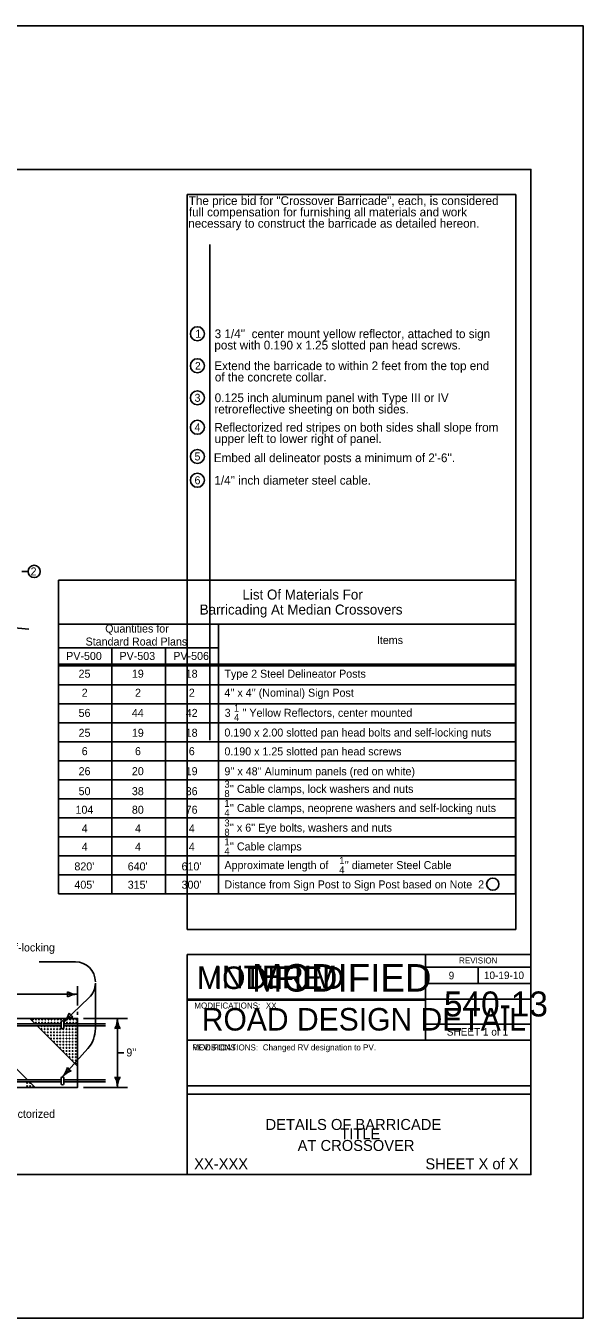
# Model space of a CAD drawing. Extents: x 228 to 3572, y -1307 to 1277.
# Drawn here: x 2457 to 3572, y -1307 to 1277 of the extents above; entities that cross this region are included whole.
import ezdxf

# ---------------------------------------------------------------- set-up
doc = ezdxf.new("R2010")
doc.units = 0
for name, color, linetype in [('dsnNonPlotable', 7, 'Continuous'), ('dsnShtPlotShapeBatchPrint', 7, 'Continuous'), ('dsnStdBlock', 7, 'Continuous'), ('dsnstdblockInterim', 7, 'Continuous'), ('dsnStdBlockModified', 7, 'Continuous'), ('dsnStdBlockNotModified', 7, 'Continuous'), ('dsnStdBorder', 7, 'Continuous'), ('dsnStdDimension', 7, 'Continuous'), ('Level 1', 7, 'Continuous'), ('Level 15', 7, 'Continuous'), ('Level 2', 7, 'Continuous'), ('Level 3', 7, 'Continuous')]:
    doc.layers.add(name, color=color, linetype=linetype)

msp = doc.modelspace()

# ---------------------------------------------------------------- linework, layer by layer
at = {"layer": 'dsnNonPlotable'}
for p, q in [((2779.5, 940), (2779.5, -530)), ((3437.5, 940), (2779.5, 940)), ((3437.5, 940), (3437.5, -530)), ((2824.5, 840), (2824.5, -151.5)), ((3437.5, -530), (2779.5, -530))]:
    msp.add_line(p, q, dxfattribs=at)
at = {"layer": 'dsnShtPlotShapeBatchPrint'}
msp.add_lwpolyline([(228, -1307), (3572, -1307), (3572, 1277), (228, 1277)], close=True, dxfattribs=at)
at = {"layer": 'dsnStdBlock'}
for p, q in [((3256.6, -580), (3256.6, -671.3)), ((3256.6, -604.9), (3467.5, -604.9)), ((3362, -604.9), (3362, -638.1)), ((3256.6, -638.1), (3467.5, -638.1)), ((2779.5, -671.3), (3256.6, -671.3)), ((3256.6, -671.3), (3256.6, -751.3)), ((3467.5, -719.1), (3256.6, -719.1)), ((2779.5, -751.3), (3467.5, -751.3)), ((2779.5, -842.3), (3467.5, -842.3))]:
    msp.add_line(p, q, dxfattribs=at)
msp.add_lwpolyline([(2779.5, -580), (3467.5, -580), (3467.5, -1020), (2779.5, -1020)], close=True, dxfattribs=at)
at = {"layer": 'dsnStdBorder'}
msp.add_lwpolyline([(332.5, 990), (3467.5, 990), (3467.5, -1020), (332.5, -1020)], close=True, dxfattribs=at)
at = {"layer": 'dsnStdDimension'}
for p, q in [((2461.1, 186.1), (2448.9, 186.1)), ((2483.6, -594.4), (2555.8, -594.4)), ((2560, -681.8), (2560, -643.5)), ((2595.8, -636.9), (2595.8, -727.9)), ((2560, -659.5), (1828, -659.5)), ((2532.4, -714.7), (2583.5, -665.8)), ((2560, -700.2), (2560, -694.3)), ((2572, -707.5), (2660, -707.5)), ((2640, -707.5), (2640, -845.5)), ((2530, -824.5), (2580.6, -767.9)), ((2652.4, -776.5), (2640, -776.5)), ((2572, -845.5), (2660, -845.5))]:
    msp.add_line(p, q, dxfattribs=at)
for centre, radius, start, end in [((2555.8, -634.4), 40, 0, 90), ((2555.8, -636.9), 40, 313.7111, 0), ((2523.8, -659.5), 16.7, 342.2666, 17.7333), ((2560, -616.3), 43.2, 241.9275, 270), ((2560, -702.6), 43.2, 90, 118.0725), ((2502.5, -683.4), 43.2, 313.7158, 341.7883), ((2558.6, -689.6), 16.7, 205.9824, 241.4491), ((2562.2, -745.9), 43.2, 105.6433, 133.7158), ((2596.8, -707.5), 43.2, 331.9275, 0), ((2683.2, -707.5), 43.2, 180, 208.0725), ((2535.8, -727.9), 60, 318.1928, 0), ((2640, -743.7), 16.7, 72.2666, 107.7334), ((2497.8, -795.7), 43.2, 318.1946, 346.2671), ((2562.2, -853.2), 43.2, 110.1221, 138.1946), ((2554.1, -797.5), 16.7, 210.4612, 245.9279), ((2640, -809.3), 16.7, 252.2666, 287.7333), ((2596.8, -845.5), 43.2, 0, 28.0725), ((2683.2, -845.5), 43.2, 151.9275, 180)]:
    msp.add_arc(centre, radius, start, end, dxfattribs=at)
at = {"layer": 'Level 15'}
for p, q in [((2779.5, -669.1), (3467.5, -669.1)), ((2779.5, -859.1), (3467.5, -859.1))]:
    msp.add_line(p, q, dxfattribs=at)
msp.add_lwpolyline([(2779.5, -580), (3467.5, -580), (3467.5, -1020), (2779.5, -1020)], close=True, dxfattribs=at)
at = {"layer": 'Level 2'}
for p, q in [((2522, 168.9), (2522, -458.4)), ((2522, 168.9), (3436.6, 168.9)), ((3436.6, 168.9), (3436.6, -458.4)), ((2018.9, 110), (2462.6, 70.9)), ((2522, 80.9), (3436.6, 80.9)), ((2842, 80.9), (2842, -458.4)), ((2522, 33.6), (2842, 33.6)), ((2629, 33.6), (2629, -458.4)), ((2736, 33.6), (2736, -458.4)), ((2522, 0.6), (3436.6, 0.6)), ((2522, -2.4), (3436.6, -2.4)), ((2522, -40.4), (3436.6, -40.4)), ((2522, -78.4), (3436.6, -78.4)), ((2522, -116.4), (3436.6, -116.4)), ((2522, -154.4), (3436.6, -154.4)), ((2522, -192.4), (3436.6, -192.4)), ((2522, -230.4), (3436.6, -230.4)), ((2522, -268.4), (3436.6, -268.4)), ((2522, -306.4), (3436.6, -306.4)), ((2522, -344.4), (3436.6, -344.4)), ((2522, -382.4), (3436.6, -382.4)), ((2522, -420.4), (3436.6, -420.4)), ((2522, -458.4), (3436.6, -458.4)), ((2475.3, -718.4), (2348, -718.4)), ((2460.2, -830.6), (2352, -722.4)), ((2479.3, -722.4), (2352, -722.4)), ((2464.4, -707.5), (2475.3, -718.4)), ((2560, -707.5), (2464.4, -707.5)), ((2475.1, -707.5), (2560, -707.5)), ((2475.3, -718.4), (2527.6, -718.4)), ((2527.6, -722.4), (2479.3, -722.4)), ((2479.3, -722.4), (2560, -803.1)), ((2527.6, -718.4), (2527.6, -714.7)), ((2527.6, -722.4), (2527.6, -718.4)), ((2527.6, -726.1), (2527.6, -722.4)), ((2532.4, -714.7), (2532.4, -718.4)), ((2616.1, -718.4), (2532.4, -718.4)), ((2532.4, -722.4), (2532.4, -718.4)), ((2532.4, -718.4), (2560, -718.4)), ((2616.1, -722.4), (2532.4, -722.4)), ((2560, -722.4), (2532.4, -722.4)), ((2532.4, -722.4), (2532.4, -726.1)), ((2560, -707.5), (2560, -718.4)), ((2560, -718.4), (2560, -707.5)), ((2560, -722.4), (2560, -749.9)), ((2560, -803.1), (2560, -722.4)), ((2527.6, -838.3), (2527.6, -826.9)), ((2532.4, -838.3), (2532.4, -826.9)), ((2332.9, -830.6), (2460.2, -830.6)), ((2464.2, -834.6), (2336.9, -834.6)), ((2464.4, -845.5), (2337.1, -845.5)), ((2347.8, -845.5), (2475.1, -845.5)), ((2527.6, -834.6), (2348, -834.6)), ((2527.6, -830.6), (2352, -830.6)), ((2475.1, -845.5), (2464.2, -834.6)), ((2616.1, -830.6), (2532.4, -830.6)), ((2616.1, -834.6), (2532.4, -834.6)), ((2560, -837.9), (2560, -845.5))]:
    msp.add_line(p, q, dxfattribs=at)
msp.add_lwpolyline([(1828, -707.5), (2560, -707.5), (2560, -845.5), (1828, -845.5)], close=True, dxfattribs=at)
for centre, radius in [((2799.9, 661.3), 14), ((2799.9, 597.3), 14), ((2799.9, 533.3), 14), ((2799.9, 474.3), 14), ((2799.9, 416), 14), ((2799.9, 368.4), 14), ((2473.4, 186.1), 12.2), ((3391, -439.2), 12.2), ((2470.7, -709.9), 0.711), ((2476.9, -709.9), 0.711), ((2476.9, -716.2), 0.711), ((2483.1, -709.9), 0.711), ((2483.1, -716.2), 0.711), ((2489.3, -709.9), 0.711), ((2489.3, -716.2), 0.711), ((2495.6, -709.9), 0.711), ((2495.6, -716.2), 0.711), ((2501.8, -709.9), 0.711), ((2501.8, -716.2), 0.711), ((2508, -709.9), 0.711), ((2508, -716.2), 0.711), ((2514.2, -709.9), 0.711), ((2514.2, -716.2), 0.711), ((2520.5, -709.9), 0.711), ((2520.5, -716.2), 0.711), ((2526.7, -709.9), 0.711), ((2526.7, -716.2), 0.711), ((2532.9, -709.9), 0.711), ((2539.1, -709.9), 0.711), ((2539.1, -716.2), 0.711), ((2545.3, -709.9), 0.711), ((2545.3, -716.2), 0.711), ((2551.6, -709.9), 0.711), ((2551.6, -716.2), 0.711), ((2557.8, -709.9), 0.711), ((2557.8, -716.2), 0.711), ((2488.1, -729.2), 0.711), ((2494.3, -729.2), 0.711), ((2494.3, -735.4), 0.711), ((2500.6, -729.2), 0.711), ((2500.6, -735.4), 0.711), ((2500.6, -741.6), 0.711), ((2506.8, -729.2), 0.711), ((2506.8, -735.4), 0.711), ((2506.8, -741.6), 0.711), ((2506.8, -747.9), 0.711), ((2513, -729.2), 0.711), ((2513, -735.4), 0.711), ((2513, -741.6), 0.711), ((2513, -747.9), 0.711), ((2519.2, -729.2), 0.711), ((2519.2, -735.4), 0.711), ((2519.2, -741.6), 0.711), ((2519.2, -747.9), 0.711), ((2525.4, -729.2), 0.711), ((2525.4, -735.4), 0.711), ((2525.4, -741.6), 0.711), ((2525.4, -747.9), 0.711), ((2531.7, -729.2), 0.711), ((2531.7, -735.4), 0.711), ((2531.7, -741.6), 0.711), ((2531.7, -747.9), 0.711), ((2537.9, -729.2), 0.711), ((2537.9, -735.4), 0.711), ((2537.9, -741.6), 0.711), ((2537.9, -747.9), 0.711), ((2544.1, -729.2), 0.711), ((2544.1, -735.4), 0.711), ((2544.1, -741.6), 0.711), ((2544.1, -747.9), 0.711), ((2550.3, -729.2), 0.711), ((2550.3, -735.4), 0.711), ((2550.3, -741.6), 0.711), ((2550.3, -747.9), 0.711), ((2556.6, -729.2), 0.711), ((2556.6, -735.4), 0.711), ((2556.6, -741.6), 0.711), ((2556.6, -747.9), 0.711), ((2513, -754.1), 0.711), ((2519.2, -754.1), 0.711), ((2519.2, -760.3), 0.711), ((2525.4, -754.1), 0.711), ((2525.4, -760.3), 0.711), ((2525.4, -766.5), 0.711), ((2531.7, -754.1), 0.711), ((2531.7, -760.3), 0.711), ((2531.7, -766.5), 0.711), ((2531.7, -772.8), 0.711), ((2537.9, -754.1), 0.711), ((2537.9, -760.3), 0.711), ((2537.9, -766.5), 0.711), ((2537.9, -772.8), 0.711), ((2544.1, -754.1), 0.711), ((2544.1, -760.3), 0.711), ((2544.1, -766.5), 0.711), ((2544.1, -772.8), 0.711), ((2550.3, -754.1), 0.711), ((2550.3, -760.3), 0.711), ((2550.3, -766.5), 0.711), ((2550.3, -772.8), 0.711), ((2556.6, -754.1), 0.711), ((2556.6, -760.3), 0.711), ((2556.6, -766.5), 0.711), ((2556.6, -772.8), 0.711), ((2537.9, -779), 0.711), ((2544.1, -779), 0.711), ((2544.1, -785.2), 0.711), ((2550.3, -779), 0.711), ((2550.3, -785.2), 0.711), ((2550.3, -791.4), 0.711), ((2556.6, -779), 0.711), ((2556.6, -785.2), 0.711), ((2556.6, -791.4), 0.711), ((2556.6, -797.6), 0.711), ((2459.2, -836.7), 0.711), ((2459.2, -842.9), 0.711), ((2465.4, -842.9), 0.711)]:
    msp.add_circle(centre, radius, dxfattribs=at)
for centre, radius, start, end in [((2471.7, 266.1), 80, 269.9999, 270), ((2481.9, -723), 0.711, 120.1157, 59.8843), ((2488.1, -723), 0.711, 120.1157, 59.8843), ((2494.3, -723), 0.711, 120.1157, 59.8843), ((2500.6, -723), 0.711, 120.1157, 59.8843), ((2506.8, -723), 0.711, 120.1157, 59.8843), ((2513, -723), 0.711, 120.1157, 59.8843), ((2519.2, -723), 0.711, 120.1157, 59.8843), ((2525.4, -723), 0.711, 120.1157, 59.8843), ((2530, -714.7), 2.4, 0, 180), ((2532.9, -716.2), 0.711, 223.7205, 136.2795), ((2537.9, -723), 0.711, 120.1157, 59.8843), ((2544.1, -723), 0.711, 120.1157, 59.8843), ((2550.3, -723), 0.711, 120.1157, 59.8843), ((2556.6, -723), 0.711, 120.1157, 59.8843), ((2530, -726.1), 2.4, 180, 0), ((2530, -826.9), 2.4, 0, 180), ((2465.4, -836.7), 0.711, 64.5167, 25.4833), ((2471.6, -842.9), 0.711, 64.5167, 25.4833), ((2530, -838.3), 2.4, 180, 0)]:
    msp.add_arc(centre, radius, start, end, dxfattribs=at)

# ---------------------------------------------------------------- texts
at = {"layer": 'dsnStdBlock'}
for s, height, p in [('REVISION', 12, (3323.6, -597.8)), ('9', 15, (3302.8, -629.4)), ('10-19-10', 15, (3373.3, -628.9)), ('540-13', 50, (3293.2, -703.8)), ('ROAD DESIGN DETAIL', 45.001, (2808.6, -731.9)), ('SHEET 1 of 1', 15, (3299, -742)), ('Changed RV designation to PV.', 12, (2930.8, -771.6)), ('DETAILS OF BARRICADE', 22, (2936.4, -930.7)), ('AT CROSSOVER', 22, (3000.6, -972.7))]:
    msp.add_text(s, height=height, dxfattribs=at).set_placement(p)
at = {"layer": 'dsnstdblockInterim'}
msp.add_text('INTERIM', height=45, dxfattribs=at).set_placement((2832.1, -647.3))
at = {"layer": 'dsnStdBlockModified'}
for s, height, p in [('MODIFIED', 45, (2799.2, -648.8)), ('MODIFICATIONS:', 12, (2789.5, -771.7))]:
    msp.add_text(s, height=height, dxfattribs=at).set_placement(p)
at = {"layer": 'dsnStdBlockNotModified'}
msp.add_text('REVISIONS:', height=12, dxfattribs=at).set_placement((2789.5, -771.7))
at = {"layer": 'dsnStdDimension'}
for s, p in [("'' Cable Clamp with self-locking", (2220, -573.8)), ("9''", (2657.7, -783.7)), ('Reflectorized', (2390.2, -906.5))]:
    msp.add_text(s, height=16, dxfattribs=at).set_placement(p)
at = {"layer": 'Level 1'}
for s, p in [('The price bid for "Crossover Barricade", each, is considered ', (2782.6, 918.7)), ('full compensation for furnishing all materials and work ', (2782.9, 896)), ('necessary to construct the barricade as detailed hereon.', (2781.5, 873.4))]:
    msp.add_text(s, height=17.5, dxfattribs=at).set_placement(p)
at = {"layer": 'Level 15'}
for s, height, p in [('MODIFIED', 55, (2908.9, -654)), ('MODIFICATIONS:', 12, (2793.8, -687.9)), ('XX', 12, (2937, -687.9)), ('TITLE', 22, (3085.9, -949.4)), ('XX-XXX', 22, (2793.4, -1009.4)), ('SHEET X of X', 22, (3256.2, -1009.4))]:
    msp.add_text(s, height=height, dxfattribs=at).set_placement(p)
at = {"layer": 'Level 2'}
msp.add_text('2', height=16, dxfattribs=at).set_placement((2466.1, 178.1))
at = {"layer": 'Level 3'}
for s, height, p in [('1', 16, (2795.7, 653.3)), ("3 1/4''  center mount yellow reflector, attached to sign ", 17.5, (2834.5, 652.6)), ('post with 0.190 x 1.25 slotted pan head screws.', 17.5, (2833.9, 629.9)), ('2', 15.2, (2795.2, 589.7)), ('Extend the barricade to within 2 feet from the top end ', 17.5, (2833.8, 588.6)), ('of the concrete collar.', 17.5, (2834.9, 565.9)), ('0.125 inch aluminum panel with Type III or IV ', 17.5, (2834.5, 524.6)), ('3', 16, (2794.2, 525.3)), ('retroreflective sheeting on both sides.', 17.5, (2833.9, 501.9)), ('4', 16, (2794.2, 466.3)), ('Reflectorized red stripes on both sides shall slope from ', 17.5, (2833.9, 465.5)), ('upper left to lower right of panel. ', 17.5, (2834.3, 442.9)), ('5', 16, (2794.1, 408)), ("Embed all delineator posts a minimum of 2'-6''.", 17.5, (2832.8, 404.6)), ('6', 16, (2794.2, 360.4)), ("1/4'' inch diameter steel cable.", 17.5, (2833.9, 359.6)), ('List Of Materials For', 20, (2890.1, 129.9)), ('Barricading At Median Crossovers', 20, (2804.6, 99.9)), ('Quantities for ', 16, (2615.4, 63.9)), ('Standard Road Plans', 16, (2576.2, 37.9)), ('Items', 16, (3159.1, 40.9)), ('PV-500', 16, (2537.3, 9.1)), ('PV-503', 16, (2644, 9.1)), ('PV-506', 16, (2751.7, 9.1)), ('25', 16, (2562.1, -26.4)), ('19', 16, (2668.8, -26.4)), ('18', 16, (2776.5, -26.4)), ('Type 2 Steel Delineator Posts', 16, (2854, -26.4)), ('2', 16, (2568.5, -64.4)), ('2', 16, (2675.1, -64.4)), ('2', 16, (2782.8, -64.4)), ("4'' x 4'' (Nominal) Sign Post", 16, (2854, -64.4)), ('56', 16, (2562.2, -104.8)), ('44', 16, (2668.8, -104.8)), ('42', 16, (2776.6, -104.8)), ('3 ', 16, (2854.5, -104.6)), ('4', 14, (2873.1, -113)), ('1', 14, (2873.1, -94.3)), (" '' Yellow Reflectors, center mounted", 16, (2884, -104.6)), ('25', 16, (2562.1, -144.5)), ('19', 16, (2668.8, -144.5)), ('18', 16, (2776.5, -144.5)), ('0.190 x 2.00 slotted pan head bolts and self-locking nuts', 16, (2854, -144)), ('6', 16, (2568.4, -181.3)), ('6', 16, (2675, -181.3)), ('6', 16, (2782.7, -181.3)), ('0.190 x 1.25 slotted pan head screws', 16, (2854, -181.7)), ('26', 16, (2562.2, -221.3)), ('20', 16, (2668.8, -221.3)), ('19', 16, (2776.5, -221.3)), ("9'' x 48'' Aluminum panels (red on white)", 16, (2854, -221.5)), ('3', 14, (2854, -246.3)), ('50', 16, (2562.2, -261.3)), ('38', 16, (2668.8, -261.3)), ('36', 16, (2776.5, -261.3)), ('8', 14, (2854, -265)), ("'' Cable clamps, lock washers and nuts", 16, (2864.9, -256.7)), ('104', 16, (2556, -298.4)), ('80', 16, (2668.8, -298.4)), ('76', 16, (2776.5, -298.4)), ('1', 14, (2854, -284.6)), ("'' Cable clamps, neoprene washers and self-locking nuts", 16, (2864.9, -294.9)), ('4', 14, (2854, -303.3)), ('3', 14, (2854, -323.8)), ('4', 16, (2568.4, -335.8)), ('4', 16, (2675.1, -335.8)), ('4', 16, (2782.8, -335.8)), ('8', 14, (2854, -342.5)), ("'' x 6'' Eye bolts, washers and nuts", 16, (2864.9, -334.2)), ('4', 16, (2568.4, -372.5)), ('4', 16, (2675.1, -372.5)), ('4', 16, (2782.8, -372.5)), ('1', 14, (2854, -361.5)), ("'' Cable clamps", 16, (2864.9, -371.8)), ('4', 14, (2854, -380.2)), ('1', 14, (3083.8, -398.8)), ("820'", 16, (2553.8, -411.7)), ("640'", 16, (2660.5, -411.7)), ("610'", 16, (2768.2, -411.7)), ('Approximate length of  ', 16, (2854, -409.1)), ('4', 14, (3083.8, -417.5)), ("'' diameter Steel Cable", 16, (3094.7, -409.1)), ("405'", 16, (2553.8, -448.3)), ("315'", 16, (2660.5, -448.3)), ("300'", 16, (2768.2, -448.3)), ('Distance from Sign Post to Sign Post based on Note  2', 16, (2854, -447.7))]:
    msp.add_text(s, height=height, dxfattribs=at).set_placement(p)

doc.saveas('drawing.dxf')
